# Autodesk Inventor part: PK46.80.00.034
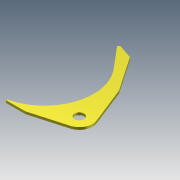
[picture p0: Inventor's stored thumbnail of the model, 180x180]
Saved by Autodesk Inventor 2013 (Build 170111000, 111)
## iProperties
Shininess: 64.0
Length Units: 11269
Angle Units: 11279
Time Units: 11290
Mass Units: 11283
Length Display Precision: 3
Angle Display Precision: 2
Compacted: True
Part Number: PK46.80.00.034
Document SubType Name: Modeling
Created: 2005-01
Material: Steel, Mild
Designer: SAlex
Manufacturer: Standard
Standards Organization: Custom
Density: 7.86 g/cm^3
Mass: 20870.5 g
Surface Area: 3215.19 cm^2
Volume: 2655.27 cm^3
Density: 0.0
Volumn: 0.0
Area: 0.0
PropertySet Name: Model Information
Control State: 0
Master: False
Checked Out: False
Checked Out Date: 2008-10-15
Last Check In Date: 2008-10-15
Author: SAlex
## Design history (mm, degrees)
sketch "Sketch1"
  geometry: L1 (-420, -188)-(-260, -188); L2 (-260, -188)-(29.987, -105.834); L3 (-20, 350)-(102.306, 40.417); L4 (-20, 350)-(-215, 635); L5 (-215, 635)-(-333.188, 675.134); L6 (-333.188, 675.134)-(-348.509, 662.278); L7 (-348.509, 662.278)-(-197.454, 482.257); L8 (-420, -177.95)-(-420, -188); L9 (-510, 220)-(-197.454, 482.257); C1 r 40 at (0, 0); A1 r 110 centre (0, 0) between (29.987, -105.834) and (102.306, 40.417); A2 r 408 centre (-510, 220) between (-420, -177.95) and (-197.454, 482.257)
  constraints: 18 end point, 4 point on circle, 3 centre point, 3 tangent, 2 perpendicular, 1 coincident, 1 horizontal, 1 other
  dimensions: "d0" = 80 diameter of C1; "d1" = 110 radius of A1; "d3" = 188 distance from line of L1 A1.centre; "d25" = 510 horizontal distance of L9.start C1.centre; "d26" = 220 vertical distance of L9.start C1.centre; "d28" = 408 radius of A2; "d29" = 90 distance from line of L8 L9.start; "d30" = 160 distance of L1.start L1.end; "d31" = 235 distance of L6.end L7.end; "d32" = 130 vertical distance of L3.start L9.start; "d33" = 490 horizontal distance of L3.start L9.start; "d34" = 295 horizontal distance of L4.end L9.start; "d35" = 130 deg angle of L8 L9; "d36" = 20 distance of L5.end L6.end; "d37" = 415 vertical distance of L4.end L9.start
extrude "Extrusion1" new body sketch "Sketch1" distance "d10" = 20; taper "d11" = 0 deg
body "Solid1"
